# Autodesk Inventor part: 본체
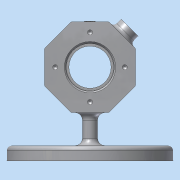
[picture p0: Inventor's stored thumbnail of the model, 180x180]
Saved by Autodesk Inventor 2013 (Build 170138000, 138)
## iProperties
Created: 2017-06
Part Number: 본체
Material: 알루미늄 6061
Document SubType Name: Modeling
Designer: dgall
Mass: 562.264 g
Surface Area: 566.116 cm^2
Volume: 207.477 cm^3
Density: 2.71 g/cm^3
Author: dgall
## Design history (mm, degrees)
sketch "스케치1"
  geometry: L1 (30, -12.426)-(12.426, -30); L2 (12.426, -30)-(-12.426, -30); L3 (-12.426, -30)-(-30, -12.426); L4 (-30, -12.426)-(-30, 12.426); L5 (-30, 12.426)-(-12.426, 30); L6 (-12.426, 30)-(12.426, 30); L7 (12.426, 30)-(30, 12.426); L8 (30, 12.426)-(30, -12.426); 3 further points
  constraints: 16 end point, 1 coincident, 1 midpoint, 1 vertical alignment, 17 other
  dimensions: "d0" = 60 distance between parallel lines of L2 L6
extrude "돌출1" new body sketch "스케치1" stored distance "d1" = 70; taper "d2" = 0 deg
sketch "스케치2"
  geometry: L1 (-35, 0)-(35, 0); L2 (-35, 16)-(-35, 30); L3 (-35, 30)-(35, 30); L4 (35, 30)-(35, 16); L5 (35, 16)-(23, 16); L6 (23, 16)-(23, 14); L7 (23, 14)-(20, 14); L8 (20, 14)-(20, 25); L9 (20, 25)-(-20, 25); L10 (-20, 25)-(-20, 14); L11 (-20, 14)-(-23, 14); L12 (-23, 14)-(-23, 16); L13 (-23, 16)-(-35, 16); L14 (-35, 16)-(-35, 0); L15 (-35, 0)-(35, 0); L16 (35, 0)-(35, 16); 2 further points
  constraints: 32 end point, 10 parallel, 4 perpendicular, 3 collinear, 2 coincident, 2 horizontal alignment, 2 vertical alignment, 1 horizontal, 1 midpoint
  dimensions: "d3" = 50 diameter of L9 L1; "d5" = 60 diameter of L3 L1; "d6" = 28 diameter of L11 L1; "d7" = 32 diameter of L13 L1; "d8" = 12 distance of L12.end L2.start; "d9" = 40 distance of L8.end L9.end; "d10" = 3 distance of L10.end L11.end
revolve "회전1" sketch "스케치2" stored, may be unused: angle "d11" = 90 deg
sketch "스케치3"
  geometry: C1 r 16 at (0, 0) reference; 1 further point
  constraints: 1 vertical alignment
  dimensions: "d13" = 23 distance of C1.centre point (0, 23)
hole "구멍1" sketch "스케치3" at (0, 23) diameter "d14" = 3.459; stored, may be unused: countersink angle "d18" = 90 deg, drill point angle "d20" = 118 deg; dims "d15" = 8, "d16" = 4, "d17" = 2, "d19" = 10
node "작업 평면1"
sketch "스케치4"
  geometry: C1 r 55 at (0, 0); 1 further point
  constraints: 1 centre point, 1 coincident
  dimensions: "d25" = 110 diameter of C1
extrude "돌출2" join sketch "스케치4" distance "d26" = 10; taper "d27" = 0 deg
sketch "스케치6"
  geometry: L1 (0, 0)-(0, 63.945); C1 r 55 at (0, 0) reference; A1 r 43 centre (0, 0) between (30.406, 30.406) and (-30.406, 30.406); A2 r 48 centre (0, 0) between (33.941, 33.941) and (-33.941, 33.941); A3 r 38 centre (0, 0) between (26.87, 26.87) and (-26.87, 26.87); A4 r 5 centre (-30.406, 30.406) between (-33.941, 33.941) and (-26.87, 26.87); A5 r 5 centre (30.406, 30.406) between (26.87, 26.87) and (33.941, 33.941); 3 further points
  constraints: 12 point on circle, 5 centre point, 4 tangent, 3 vertical alignment, 2 end point, 1 concentric, 1 horizontal alignment, 1 vertical
  dimensions: "d42" = 63.94496 distance of L1.start L1.end; "d43" = 43 radius of A1; "d44" = 5 radial gap between concentric circles of A1 A2; "d45" = 5 radial gap between concentric circles of A3 A1; "d46" = 30.40559 horizontal distance of L1.start A4.centre; "d47" = 30.40559 horizontal distance of L1.start A1.start; "d48" = 48 distance of L1.start point (0, 48)
extrude "돌출3" cut sketch "스케치6" distance "d49" = 3; taper "d50" = 0 deg
sketch "스케치7"
  geometry: A1 r 48 centre (0, 0) between (33.941, 33.941) and (-33.941, 33.941) reference; A2 r 5 centre (-30.406, 30.406) between (-33.941, 33.941) and (-26.87, 26.87) reference; A3 r 38 centre (0, 0) between (26.87, 26.87) and (-26.87, 26.87) reference; A4 r 5 centre (30.406, 30.406) between (26.87, 26.87) and (33.941, 33.941) reference; A5 r 48 centre (0, 0) between (33.941, 33.941) and (-33.941, 33.941) reference; A6 r 5 centre (-30.406, 30.406) between (-33.941, 33.941) and (-26.87, 26.87) reference; A7 r 38 centre (0, 0) between (26.87, 26.87) and (-26.87, 26.87) reference; A8 r 5 centre (30.406, 30.406) between (26.87, 26.87) and (33.941, 33.941) reference; A9 r 2 centre (-30.406, 30.406) between (-31.82, 31.82) and (-28.991, 28.991); A10 r 45 centre (0, 0) between (31.82, 31.82) and (-31.82, 31.82); A11 r 2 centre (30.406, 30.406) between (28.991, 28.991) and (31.82, 31.82); A12 r 41 centre (0, 0) between (28.991, 28.991) and (-28.991, 28.991)
  constraints: 8 point on circle, 4 centre point, 3 other
  dimensions: "d51" = 2 radius of A9
extrude "돌출4" cut sketch "스케치7" stored distance "d53" = 3; taper "d54" = 0 deg
sketch "스케치8"
  geometry: L1 (-24, 5)-(24, 5); L2 (24, -5)-(15.013, -5); L3 (15.013, -5)-(-24, -5); A1 r 38 centre (0, 0) between (-26.87, -26.87) and (26.87, -26.87) reference; A2 r 48 centre (0, 0) between (-33.941, -33.941) and (33.941, -33.941) reference; A3 r 5 centre (24, 0) between (24, -5) and (24, 5); A4 r 5 centre (-24, 0) between (-24, 5) and (-24, -5); 1 further point
  constraints: 6 end point, 4 point on circle, 4 tangent, 2 centre point, 1 equal radius, 1 horizontal, 1 horizontal alignment, 1 midpoint, 1 parallel, 1 vertical alignment
  dimensions: "d55" = 48 distance of A3.centre A4.centre; "d57" = 5 radius of A4
extrude "돌출5" join sketch "스케치8" stored distance "d58" = 3; taper "d59" = 0 deg
sketch "스케치10"
  geometry: L1 (0, 0)-(38.902, 0); L2 (12.426, 30)-(30, 12.426) reference; L3 (0, 0)-(21.213, 21.213); 1 further point
  constraints: 4 end point, 1 coincident, 1 horizontal, 1 midpoint, 1 perpendicular
  dimensions: "d62" = 38.90183 distance of L1.start L1.end
sketch "스케치11"
  geometry: C1 r 8 at (35, 12.426); 1 further point
  constraints: 1 centre point, 1 coincident
  dimensions: "d63" = 16 diameter of C1
extrude "돌출6" join sketch "스케치11" distance "d65" = 7; taper "d66" = 0 deg
sketch "스케치12"
  geometry: C1 r 8 at (0, 0) reference; 1 further point
  constraints: 1 coincident
hole "구멍2" sketch "스케치12" at (0, 0) diameter "d67" = 8; stored, may be unused: countersink angle "d71" = 90 deg, drill point angle "d73" = 118 deg; dims "d68" = 8, "d69" = 4, "d70" = 2, "d72" = 10
sketch "스케치13"
  geometry: L1 (70, 42.426)-(0, 42.426) reference; 2 further points
  constraints: 1 other
  dimensions: "d74" = 35 horizontal distance of point (35, 12.508) L1.end; "d75" = 30 vertical distance of point (35, 12.426) L1.end (derived)
fillet "모깎기2" dims "d78" = 5
fillet "모깎기3" dims "d79" = 3
fillet "모깎기4" dims "d80" = 3
fillet "모깎기5" dims "d81" = 0.3
chamfer "모따기1" distance "d82" = 1; stored, may be unused: second distance "d83" = 2, angle "d84" = 45 deg
chamfer "모따기2" distance "d85" = 1; stored, may be unused: second distance "d86" = 2, angle "d87" = 45 deg
fillet "모깎기6" dims "d88" = 1
feature "엠보싱1" dims "d0" = 60, "d3" = 50, "d5" = 60, "d6" = 28, "d7" = 32, "d8" = 12, "d9" = 40, "d10" = 3, "d89" = 0.5, "d90" = 0
node "솔리드1"
pattern_circular "원형 패턴1" dims angle "d22" = 360 deg
mirror "대칭1"
mirror "대칭2"
node "투영된 루프1"
other parameters: "d24" = -62
